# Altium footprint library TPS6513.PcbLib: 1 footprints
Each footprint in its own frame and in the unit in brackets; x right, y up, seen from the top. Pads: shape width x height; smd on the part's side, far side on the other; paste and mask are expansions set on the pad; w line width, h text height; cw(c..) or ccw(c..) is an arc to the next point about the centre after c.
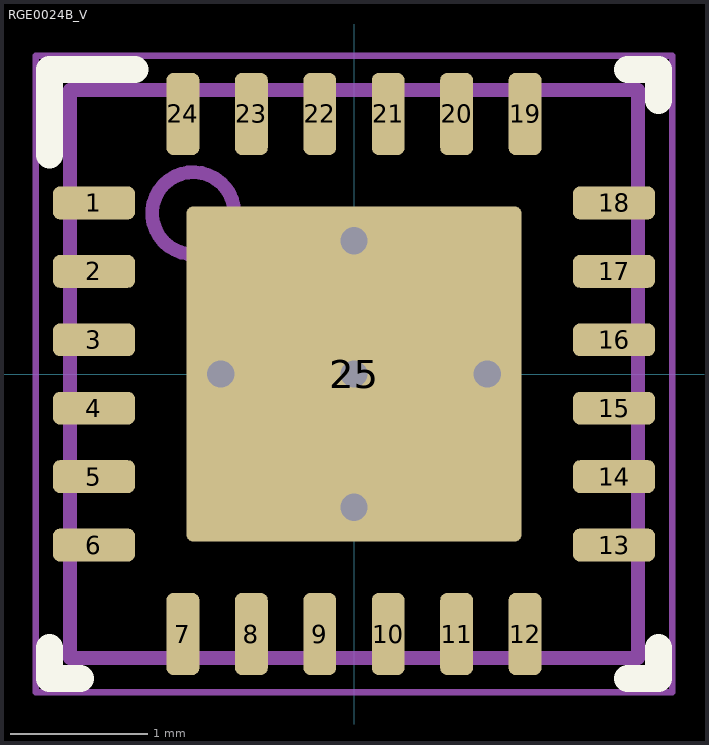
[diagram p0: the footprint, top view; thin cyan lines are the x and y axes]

## RGE0024B_V [mm] "QFN, 24-Leads, Body 4x4mm, Pitch 0.5mm, Thermal Pad 2.45x2.45mm"
height 1
pads (25):
  rrect42% 0.6x0.24 smd: 1(-1.9,1.25) 2(-1.9,0.75) 3(-1.9,0.25) 4(-1.9,-0.25) 5(-1.9,-0.75) 6(-1.9,-1.25) 13(1.9,-1.25) 14(1.9,-0.75) 15(1.9,-0.25) 16(1.9,0.25) 17(1.9,0.75) 18(1.9,1.25)
  rrect42% 0.24x0.6 smd: 7(-1.25,-1.9) 8(-0.75,-1.9) 9(-0.25,-1.9) 10(0.25,-1.9) 11(0.75,-1.9) 12(1.25,-1.9) 19(1.25,1.9) 20(0.75,1.9) 21(0.25,1.9) 22(-0.25,1.9) 23(-0.75,1.9) 24(-1.25,1.9)
  rrect4% 2.45x2.45 smd paste-1.225: 25(0,0)
via 0,0.975 diameter 0.5 hole 0.2
via -0.975,0 diameter 0.5 hole 0.2
via 0,0 diameter 0.5 hole 0.2
via 0.975,0 diameter 0.5 hole 0.2
via 0,-0.975 diameter 0.5 hole 0.2
Top Overlay:
  lines w0.2: -2.225,-2 -2.225,-2.225 -2,-2.225 ; -2.225,1.6 -2.225,2.225 -1.6,2.225 ; 2,-2.225 2.225,-2.225 2.225,-2 ; 2,2.225 2.225,2.225 2.225,2
Top Paste:
  rectangle: 0.1,0.1 1.184,1.184
  region: -0.1,1.184 -1.184,1.184 -1.184,0.1 -0.1,0.1
  region: -0.1,-0.1 -1.184,-0.1 -1.184,-1.184 -0.1,-1.184
  rectangle: 0.1,-1.184 1.184,-0.1
Mechanical 1:
  text ".Designator" at -1.854,-0.508 h1.02
Mechanical 13:
  circle w0.1: c-1.175,1.175 r0.3
  lines w0.1: -2.075,-2.075 -2.075,2.075 2.075,2.075 2.075,-2.075 -2.075,-2.075
Mechanical 15:
  lines w0.05: -2.325,-2.325 -2.325,2.325 2.325,2.325 2.325,-2.325 -2.325,-2.325
  lines w0.1: -0.5,0 0.5,0 ; 0,-0.5 0,0.5
3D body: height 1, standoff 0, extent -2.075,-2.075 2.075,2.075
3D body: height 1.01, standoff 0.5, extent -1.474,0.876 -0.876,1.474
